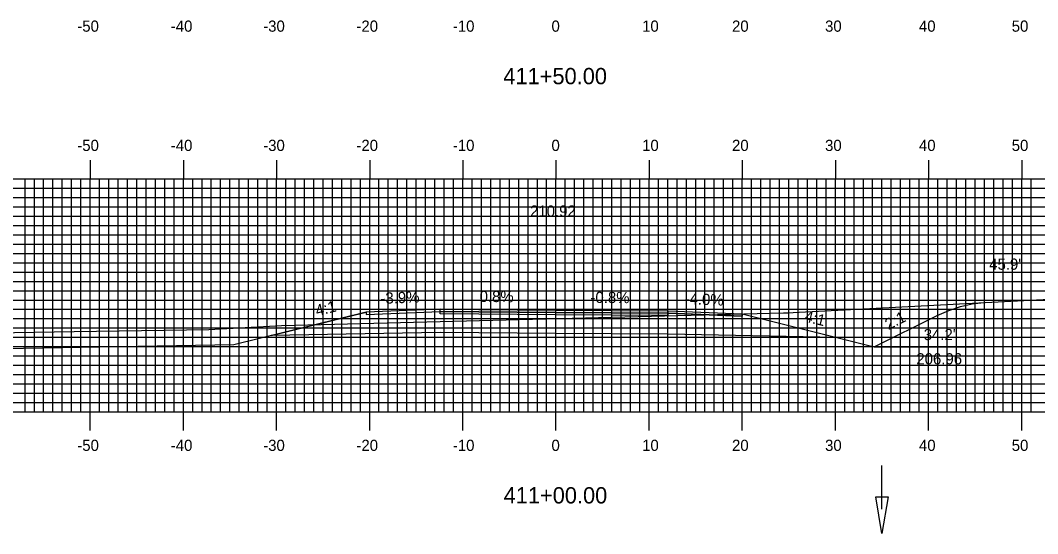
# Model space of a CAD drawing. Extents: x 853316 to 853659, y 364785 to 365005.
# Drawn here: x 853424.3 to 853533.5, y 364895.1 to 364950.3 of the extents above; entities that cross this region are included whole.
import ezdxf

# ---------------------------------------------------------------- set-up
doc = ezdxf.new("R2010")
doc.units = 0
for name, color, linetype in [('ANNOTATION', 7, 'Continuous'), ('D_Drainage_Ditch_Line', 7, 'Continuous'), ('D_Roadway_Centerline', 7, 'Continuous'), ('D_Roadway_Centerline_Text', 7, 'Continuous'), ('D_Roadway_Edge_Shoulder', 7, 'Continuous'), ('D_Roadway_Edge_TW', 7, 'Continuous'), ('D_Roadway_Pavement', 7, 'Continuous'), ('D_Roadway_SlopeLines', 7, 'Continuous'), ('D_Roadway_SubGrade', 7, 'Continuous'), ('D_Text_Standard', 7, 'Continuous'), ('H_V ANNOTATION', 7, 'Continuous'), ('MAJOR', 7, 'Continuous'), ('MINOR', 7, 'Continuous'), ('PDRAIN', 7, 'Continuous'), ('S_Roadway_Centerline', 7, 'Continuous')]:
    doc.layers.add(name, color=color, linetype=linetype)

msp = doc.modelspace()

# ---------------------------------------------------------------- linework, layer by layer
at = {"layer": 'D_Drainage_Ditch_Line'}
msp.add_line((853516.76, 364897.77), (853516.76, 364902.47), dxfattribs=at)
msp.add_lwpolyline([(853516.11, 364899.09), (853517.42, 364899.09), (853516.76, 364895.15)], close=True, dxfattribs=at)
at = {"layer": 'D_Roadway_Edge_Shoulder'}
for points in [[(853469.32, 364919.25), (853461.39, 364918.94), (853461.39, 364918.69), (853469.32, 364919)], [(853493.76, 364919.06), (853501.76, 364918.74), (853501.76, 364918.49), (853493.76, 364918.81)]]:
    msp.add_lwpolyline(points, close=True, dxfattribs=at)
at = {"layer": 'D_Roadway_Edge_TW'}
msp.add_lwpolyline([(853469.32, 364919), (853469.32, 364919.25), (853481.76, 364919.15), (853493.76, 364919.06), (853493.76, 364918.81), (853481.76, 364918.9)], close=True, dxfattribs=at)
at = {"layer": 'D_Roadway_Pavement'}
msp.add_lwpolyline([(853469.32, 364918.75), (853469.32, 364919), (853481.76, 364918.9), (853493.76, 364918.81), (853493.76, 364918.56), (853481.76, 364918.65)], close=True, dxfattribs=at)
at = {"layer": 'D_Roadway_SlopeLines'}
for points in [[(853515.93, 364915.19), (853522.68, 364918.57), (853523.93, 364919.12), (853525.18, 364919.54), (853526.43, 364919.81), (853527.68, 364919.95)], [(853461.39, 364918.94), (853447.17, 364915.41), (853371.17, 364914.1)], [(853501.76, 364918.74), (853515.93, 364915.19)]]:
    msp.add_lwpolyline(points, dxfattribs=at)
at = {"layer": 'D_Roadway_SubGrade'}
msp.add_lwpolyline([(853469.32, 364916.75), (853451.18, 364916.41), (853461.39, 364918.94), (853461.39, 364918.69), (853469.32, 364919), (853481.76, 364918.9), (853493.76, 364918.81), (853501.76, 364918.49), (853501.76, 364918.74), (853511.93, 364916.19), (853493.76, 364916.56), (853481.76, 364916.65)], close=True, dxfattribs=at)
at = {"layer": 'MAJOR'}
for p, q in [((853431.76, 364935.24), (853431.76, 364933.23)), ((853441.76, 364935.24), (853441.76, 364933.23)), ((853451.76, 364935.24), (853451.76, 364933.23)), ((853461.76, 364935.24), (853461.76, 364933.23)), ((853471.76, 364935.24), (853471.76, 364933.23)), ((853481.76, 364935.24), (853481.76, 364933.23)), ((853491.76, 364935.24), (853491.76, 364933.23)), ((853501.76, 364935.24), (853501.76, 364933.23)), ((853511.76, 364935.24), (853511.76, 364933.23)), ((853521.76, 364935.24), (853521.76, 364933.23)), ((853531.76, 364935.24), (853531.76, 364933.23)), ((853341.76, 364933.23), (853621.76, 364933.23)), ((853341.76, 364933.23), (853621.76, 364933.23)), ((853431.76, 364908.23), (853431.76, 364933.23)), ((853441.76, 364908.23), (853441.76, 364933.23)), ((853451.76, 364908.23), (853451.76, 364933.23)), ((853461.76, 364908.23), (853461.76, 364933.23)), ((853471.76, 364908.23), (853471.76, 364933.23)), ((853481.76, 364908.23), (853481.76, 364933.23)), ((853491.76, 364908.23), (853491.76, 364933.23)), ((853501.76, 364908.23), (853501.76, 364933.23)), ((853511.76, 364908.23), (853511.76, 364933.23)), ((853521.76, 364908.23), (853521.76, 364933.23)), ((853531.76, 364908.23), (853531.76, 364933.23)), ((853341.76, 364928.23), (853621.76, 364928.23)), ((853341.76, 364923.23), (853621.76, 364923.23)), ((853341.76, 364918.23), (853621.76, 364918.23)), ((853341.76, 364913.23), (853621.76, 364913.23)), ((853341.76, 364908.23), (853621.76, 364908.23)), ((853341.76, 364908.23), (853621.76, 364908.23)), ((853431.76, 364906.23), (853431.76, 364908.23)), ((853441.76, 364906.23), (853441.76, 364908.23)), ((853451.76, 364906.23), (853451.76, 364908.23)), ((853461.76, 364906.23), (853461.76, 364908.23)), ((853471.76, 364906.23), (853471.76, 364908.23)), ((853481.76, 364906.23), (853481.76, 364908.23)), ((853491.76, 364906.23), (853491.76, 364908.23)), ((853501.76, 364906.23), (853501.76, 364908.23)), ((853511.76, 364906.23), (853511.76, 364908.23)), ((853521.76, 364906.23), (853521.76, 364908.23)), ((853531.76, 364906.23), (853531.76, 364908.23))]:
    msp.add_line(p, q, dxfattribs=at)
at = {"layer": 'MINOR'}
for p, q in [((853424.76, 364908.23), (853424.76, 364933.23)), ((853425.76, 364908.23), (853425.76, 364933.23)), ((853426.76, 364908.23), (853426.76, 364933.23)), ((853427.76, 364908.23), (853427.76, 364933.23)), ((853428.76, 364908.23), (853428.76, 364933.23)), ((853429.76, 364908.23), (853429.76, 364933.23)), ((853430.76, 364908.23), (853430.76, 364933.23)), ((853432.76, 364908.23), (853432.76, 364933.23)), ((853433.76, 364908.23), (853433.76, 364933.23)), ((853434.76, 364908.23), (853434.76, 364933.23)), ((853435.76, 364908.23), (853435.76, 364933.23)), ((853436.76, 364908.23), (853436.76, 364933.23)), ((853437.76, 364908.23), (853437.76, 364933.23)), ((853438.76, 364908.23), (853438.76, 364933.23)), ((853439.76, 364908.23), (853439.76, 364933.23)), ((853440.76, 364908.23), (853440.76, 364933.23)), ((853442.76, 364908.23), (853442.76, 364933.23)), ((853443.76, 364908.23), (853443.76, 364933.23)), ((853444.76, 364908.23), (853444.76, 364933.23)), ((853445.76, 364908.23), (853445.76, 364933.23)), ((853446.76, 364908.23), (853446.76, 364933.23)), ((853447.76, 364908.23), (853447.76, 364933.23)), ((853448.76, 364908.23), (853448.76, 364933.23)), ((853449.76, 364908.23), (853449.76, 364933.23)), ((853450.76, 364908.23), (853450.76, 364933.23)), ((853452.76, 364908.23), (853452.76, 364933.23)), ((853453.76, 364908.23), (853453.76, 364933.23)), ((853454.76, 364908.23), (853454.76, 364933.23)), ((853455.76, 364908.23), (853455.76, 364933.23)), ((853456.76, 364908.23), (853456.76, 364933.23)), ((853457.76, 364908.23), (853457.76, 364933.23)), ((853458.76, 364908.23), (853458.76, 364933.23)), ((853459.76, 364908.23), (853459.76, 364933.23)), ((853460.76, 364908.23), (853460.76, 364933.23)), ((853462.76, 364908.23), (853462.76, 364933.23)), ((853463.76, 364908.23), (853463.76, 364933.23)), ((853464.76, 364908.23), (853464.76, 364933.23)), ((853465.76, 364908.23), (853465.76, 364933.23)), ((853466.76, 364908.23), (853466.76, 364933.23)), ((853467.76, 364908.23), (853467.76, 364933.23)), ((853468.76, 364908.23), (853468.76, 364933.23)), ((853469.76, 364908.23), (853469.76, 364933.23)), ((853470.76, 364908.23), (853470.76, 364933.23)), ((853472.76, 364908.23), (853472.76, 364933.23)), ((853473.76, 364908.23), (853473.76, 364933.23)), ((853474.76, 364908.23), (853474.76, 364933.23)), ((853475.76, 364908.23), (853475.76, 364933.23)), ((853476.76, 364908.23), (853476.76, 364933.23)), ((853477.76, 364908.23), (853477.76, 364933.23)), ((853478.76, 364908.23), (853478.76, 364933.23)), ((853479.76, 364908.23), (853479.76, 364933.23)), ((853480.76, 364908.23), (853480.76, 364933.23)), ((853482.76, 364908.23), (853482.76, 364933.23)), ((853483.76, 364908.23), (853483.76, 364933.23)), ((853484.76, 364908.23), (853484.76, 364933.23)), ((853485.76, 364908.23), (853485.76, 364933.23)), ((853486.76, 364908.23), (853486.76, 364933.23)), ((853487.76, 364908.23), (853487.76, 364933.23)), ((853488.76, 364908.23), (853488.76, 364933.23)), ((853489.76, 364908.23), (853489.76, 364933.23)), ((853490.76, 364908.23), (853490.76, 364933.23)), ((853492.76, 364908.23), (853492.76, 364933.23)), ((853493.76, 364908.23), (853493.76, 364933.23)), ((853494.76, 364908.23), (853494.76, 364933.23)), ((853495.76, 364908.23), (853495.76, 364933.23)), ((853496.76, 364908.23), (853496.76, 364933.23)), ((853497.76, 364908.23), (853497.76, 364933.23)), ((853498.76, 364908.23), (853498.76, 364933.23)), ((853499.76, 364908.23), (853499.76, 364933.23)), ((853500.76, 364908.23), (853500.76, 364933.23)), ((853502.76, 364908.23), (853502.76, 364933.23)), ((853503.76, 364908.23), (853503.76, 364933.23)), ((853504.76, 364908.23), (853504.76, 364933.23)), ((853505.76, 364908.23), (853505.76, 364933.23)), ((853506.76, 364908.23), (853506.76, 364933.23)), ((853507.76, 364908.23), (853507.76, 364933.23)), ((853508.76, 364908.23), (853508.76, 364933.23)), ((853509.76, 364908.23), (853509.76, 364933.23)), ((853510.76, 364908.23), (853510.76, 364933.23)), ((853512.76, 364908.23), (853512.76, 364933.23)), ((853513.76, 364908.23), (853513.76, 364933.23)), ((853514.76, 364908.23), (853514.76, 364933.23)), ((853515.76, 364908.23), (853515.76, 364933.23)), ((853516.76, 364908.23), (853516.76, 364933.23)), ((853517.76, 364908.23), (853517.76, 364933.23)), ((853518.76, 364908.23), (853518.76, 364933.23)), ((853519.76, 364908.23), (853519.76, 364933.23)), ((853520.76, 364908.23), (853520.76, 364933.23)), ((853522.76, 364908.23), (853522.76, 364933.23)), ((853523.76, 364908.23), (853523.76, 364933.23)), ((853524.76, 364908.23), (853524.76, 364933.23)), ((853525.76, 364908.23), (853525.76, 364933.23)), ((853526.76, 364908.23), (853526.76, 364933.23)), ((853527.76, 364908.23), (853527.76, 364933.23)), ((853528.76, 364908.23), (853528.76, 364933.23)), ((853529.76, 364908.23), (853529.76, 364933.23)), ((853530.76, 364908.23), (853530.76, 364933.23)), ((853532.76, 364908.23), (853532.76, 364933.23)), ((853341.76, 364932.23), (853621.76, 364932.23)), ((853341.76, 364931.23), (853621.76, 364931.23)), ((853341.76, 364930.23), (853621.76, 364930.23)), ((853341.76, 364929.23), (853621.76, 364929.23)), ((853341.76, 364927.23), (853621.76, 364927.23)), ((853341.76, 364926.23), (853621.76, 364926.23)), ((853341.76, 364925.23), (853621.76, 364925.23)), ((853341.76, 364924.23), (853621.76, 364924.23)), ((853341.76, 364922.23), (853621.76, 364922.23)), ((853341.76, 364921.23), (853621.76, 364921.23)), ((853341.76, 364920.23), (853621.76, 364920.23)), ((853341.76, 364919.23), (853621.76, 364919.23)), ((853341.76, 364917.23), (853621.76, 364917.23)), ((853341.76, 364916.23), (853621.76, 364916.23)), ((853341.76, 364915.23), (853621.76, 364915.23)), ((853341.76, 364914.23), (853621.76, 364914.23)), ((853341.76, 364912.23), (853621.76, 364912.23)), ((853341.76, 364911.23), (853621.76, 364911.23)), ((853341.76, 364910.23), (853621.76, 364910.23)), ((853341.76, 364909.23), (853621.76, 364909.23))]:
    msp.add_line(p, q, dxfattribs=at)
at = {"layer": 'PDRAIN'}
msp.add_line((853515.93, 364915.19), (853526.7, 364915.19), dxfattribs=at)
at = {"layer": 'S_Roadway_Centerline'}
msp.add_lwpolyline([(853341.76, 364914.32), (853347.1, 364914.42), (853353.88, 364914.55), (853369.34, 364915.29), (853370.22, 364915.33), (853385.95, 364915.91), (853387.75, 364916), (853390.71, 364916.13), (853393.68, 364916.23), (853430.05, 364916.84), (853444.48, 364917.05), (853452.3, 364917.5), (853506.17, 364918.85), (853506.72, 364918.86), (853507.22, 364918.88), (853507.88, 364918.91), (853540.24, 364920.6), (853555.34, 364921.1), (853558.6, 364921.29), (853584.78, 364924.26), (853591.18, 364924.71), (853605.32, 364925.33), (853607.63, 364925.51), (853621.76, 364926.36)], dxfattribs=at)

# ---------------------------------------------------------------- texts
at = {"layer": 'ANNOTATION'}
for s, rotation, p in [('-3.9%', 2.228, (853462.94, 364919.81)), ('0.8%', 359.5373, (853473.56, 364920.02)), ('-0.8%', 359.5373, (853485.46, 364919.92)), ('-4.0%', 357.7094, (853495.55, 364919.79)), ('4:1', 13.9525, (853456.1, 364918.49)), ('4:1', 345.9638, (853508.35, 364917.95)), ('2:1', 26.5651, (853517.45, 364916.99))]:
    msp.add_text(s, height=1.2, rotation=rotation, dxfattribs=at).set_placement(p)
for s, p in [("34.2'", (853521.24, 364915.92)), ('206.96', (853520.45, 364913.32))]:
    msp.add_text(s, height=1.2, dxfattribs=at).set_placement(p)
at = {"layer": 'D_Roadway_Centerline'}
for s, p in [('C', (853481.75, 364919.15)), ('L', (853481.76, 364919.15))]:
    msp.add_text(s, height=0.0146, dxfattribs=at).set_placement(p)
at = {"layer": 'D_Roadway_Centerline_Text'}
msp.add_text('210.92', height=1.2, dxfattribs=at).set_placement((853478.98, 364929.18))
at = {"layer": 'D_Text_Standard'}
msp.add_text("45.9'", height=1.2, dxfattribs=at).set_placement((853528.27, 364923.48))
at = {"layer": 'H_V ANNOTATION'}
for s, height, p in [('-50', 1.2, (853430.37, 364949.03)), ('-40', 1.2, (853440.41, 364949.03)), ('-30', 1.2, (853450.33, 364949.03)), ('-20', 1.2, (853460.34, 364949.03)), ('-10', 1.2, (853470.69, 364949.03)), ('0', 1.2, (853481.28, 364949.03)), ('10', 1.2, (853491.01, 364949.03)), ('20', 1.2, (853500.66, 364949.03)), ('30', 1.2, (853510.65, 364949.03)), ('40', 1.2, (853520.73, 364949.03)), ('50', 1.2, (853530.69, 364949.03)), ('411+50.00', 1.75, (853476.11, 364943.39)), ('-50', 1.2, (853430.37, 364936.23)), ('-40', 1.2, (853440.41, 364936.23)), ('-30', 1.2, (853450.33, 364936.23)), ('-20', 1.2, (853460.34, 364936.23)), ('-10', 1.2, (853470.69, 364936.23)), ('0', 1.2, (853481.28, 364936.23)), ('10', 1.2, (853491.01, 364936.23)), ('20', 1.2, (853500.66, 364936.23)), ('30', 1.2, (853510.65, 364936.23)), ('40', 1.2, (853520.73, 364936.23)), ('50', 1.2, (853530.69, 364936.23)), ('-50', 1.2, (853430.37, 364904.03)), ('-40', 1.2, (853440.41, 364904.03)), ('-30', 1.2, (853450.33, 364904.03)), ('-20', 1.2, (853460.34, 364904.03)), ('-10', 1.2, (853470.69, 364904.03)), ('0', 1.2, (853481.28, 364904.03)), ('10', 1.2, (853491.01, 364904.03)), ('20', 1.2, (853500.66, 364904.03)), ('30', 1.2, (853510.65, 364904.03)), ('40', 1.2, (853520.73, 364904.03)), ('50', 1.2, (853530.69, 364904.03)), ('411+00.00', 1.75, (853476.14, 364898.39))]:
    msp.add_text(s, height=height, dxfattribs=at).set_placement(p)

doc.saveas('drawing.dxf')
